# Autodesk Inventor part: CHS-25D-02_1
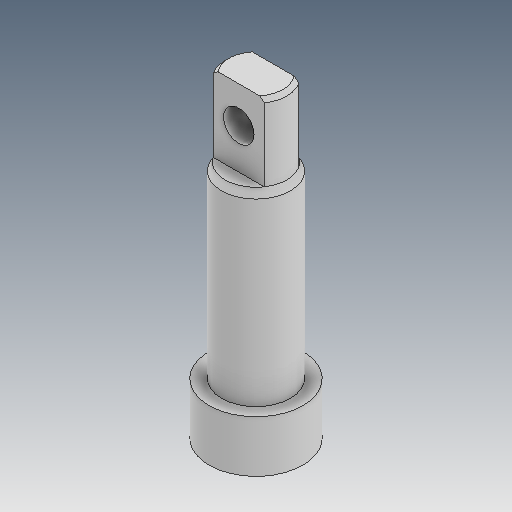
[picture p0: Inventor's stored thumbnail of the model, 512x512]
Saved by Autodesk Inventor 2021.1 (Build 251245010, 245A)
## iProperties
Created: 2019-04
Part Number: CHS-25D-02_1
Material: Ogólny
Document SubType Name: Modeling
Designer: user
Density: 1 g/cm^3
Appearance: Domyślna
Author: user
Revision Number: ÈÎºÎ
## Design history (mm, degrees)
feature "ÊäÈë1"
feature "ÊäÈë2"
node "Bryła1"
node "Bryła2"
